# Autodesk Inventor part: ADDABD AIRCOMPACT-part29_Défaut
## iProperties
Shininess: 64.0
Length Units: 11269
Angle Units: 11279
Time Units: 11290
Mass Units: 11283
Length Display Precision: 3
Angle Display Precision: 2
Compacted: True
Part Number: ADDABD AIRCOMPACT-part29_Défaut
Document SubType Name: Modeling
Created: 2006-01
Material: Par défaut
Designer: riri
Density: 0.0
Volumn: 0.0
Area: 0.0
PropertySet Name: Model Information
Control State: 0
Master: False
Checked Out: False
Author: riri
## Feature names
1. Base1
